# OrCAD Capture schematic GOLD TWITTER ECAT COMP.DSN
size A4; title: GTWIECAT
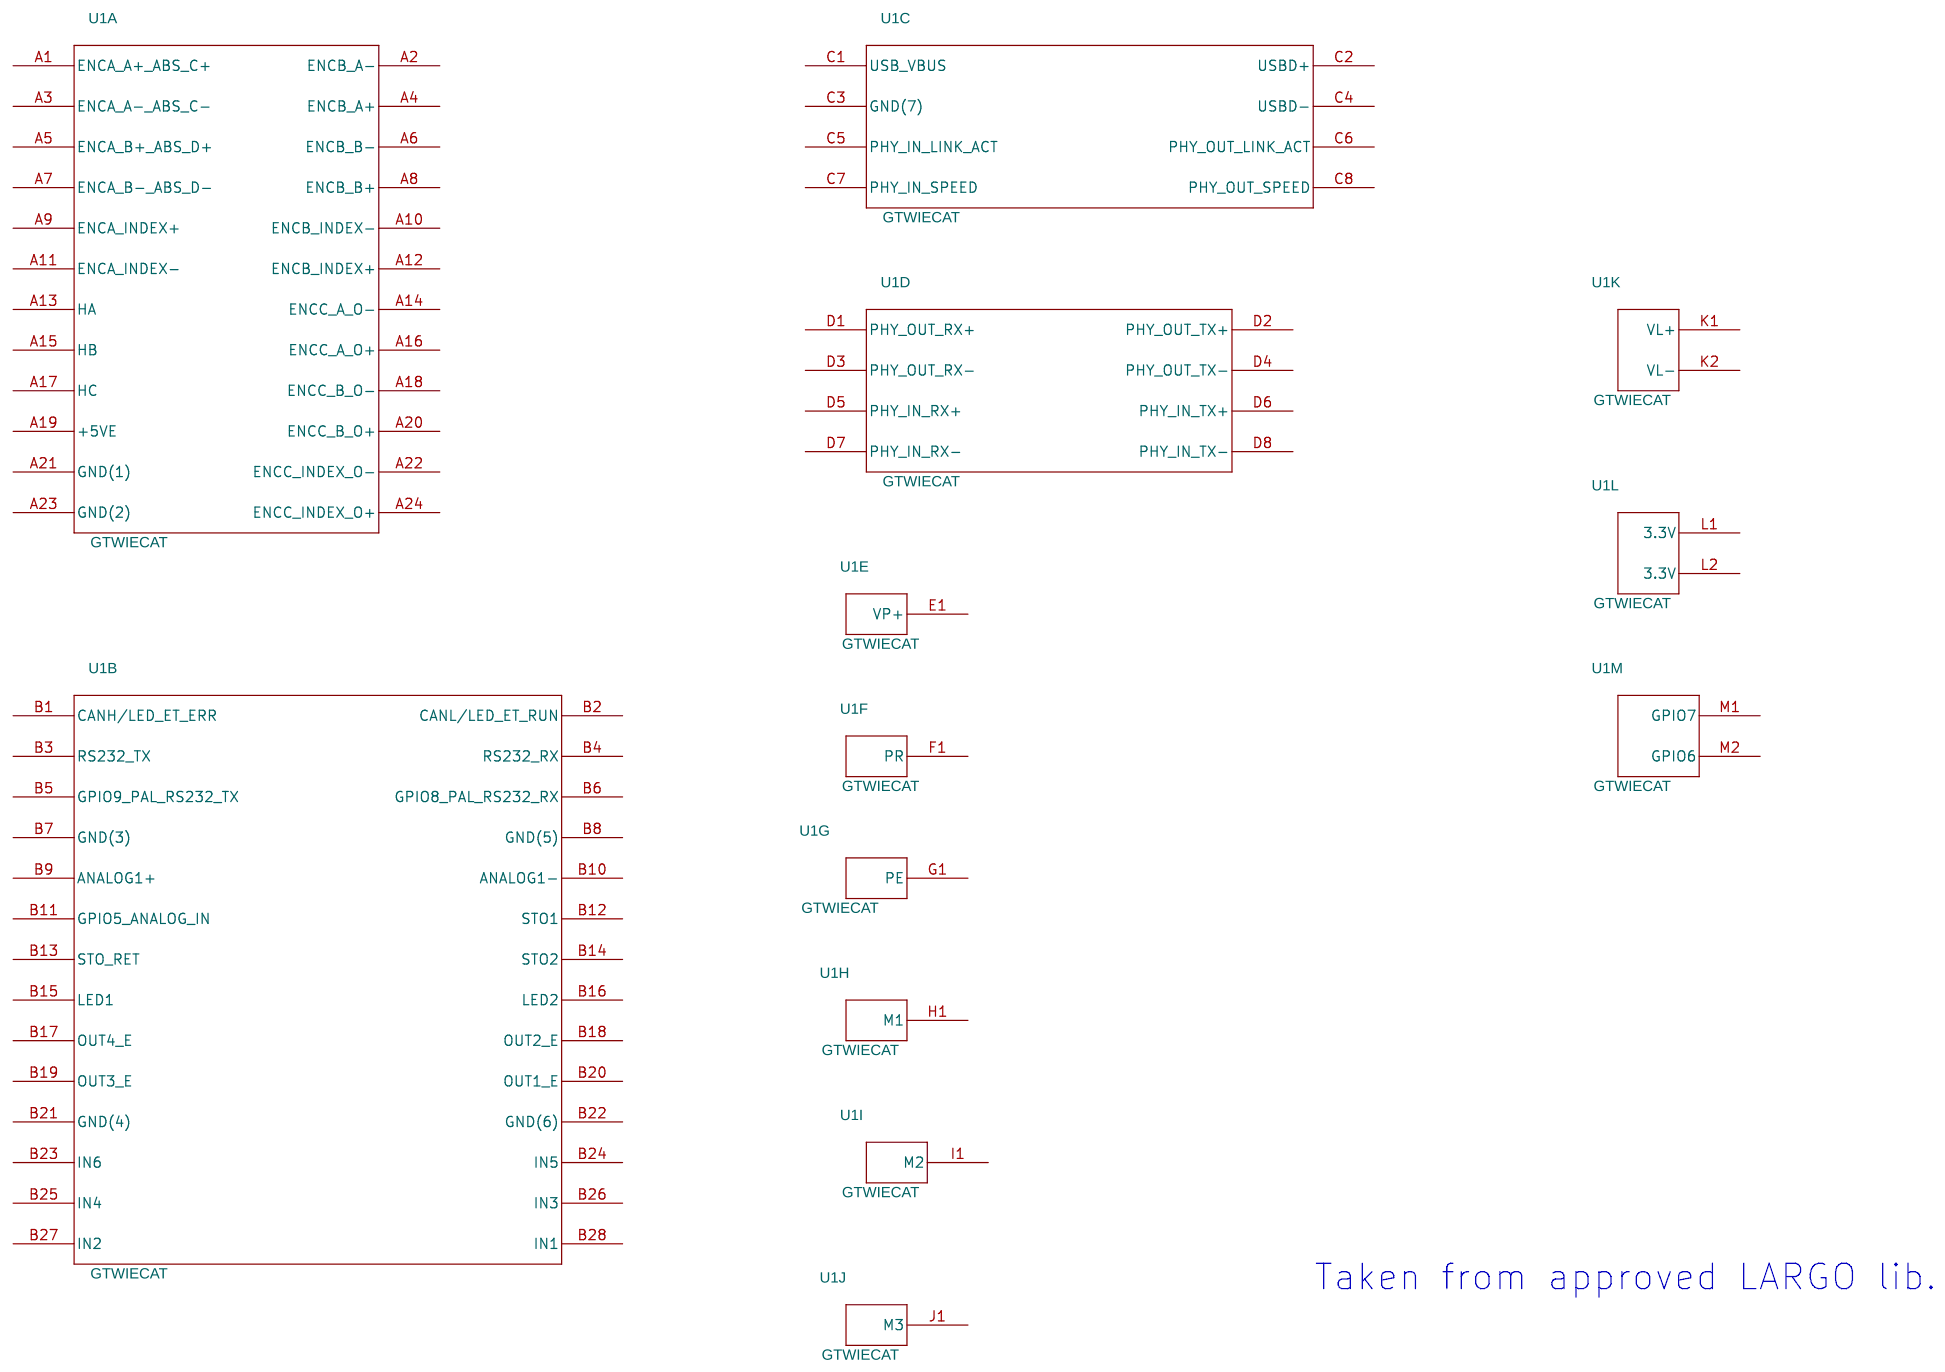
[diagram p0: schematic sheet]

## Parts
U1  GTWIECAT  [NANO_V1]  (sections A,B,C,D,E,F,G,H,I,J,K,L,M)

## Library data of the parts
U1 = GTWIECAT_GTWIECAT

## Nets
3.3V: U1.L1(3.3V) U1.L2(3.3V)
+5VE: U1.A19(+5VE)
GND(1): U1.A21(GND(1))
GND(2): U1.A23(GND(2))
GND(3): U1.B7(GND(3))
GND(4): U1.B21(GND(4))
GND(5): U1.B8(GND(5))
GND(6): U1.B22(GND(6))
GND(7): U1.C3(GND(7))
PE: U1.G1(PE)
PR: U1.F1(PR)
VL+: U1.K1(VL+)
VL-: U1.K2(VL-)
VP+: U1.E1(VP+)

Not connected (* = marked no-connect by the designer): U1 A1(ENCA_A+_ABS_C+) A2(ENCB_A-) A3(ENCA_A-_ABS_C-) A4(ENCB_A+) A5(ENCA_B+_ABS_D+) A6(ENCB_B-) A7(ENCA_B-_ABS_D-) A8(ENCB_B+) A9(ENCA_INDEX+) A10(ENCB_INDEX-) A11(ENCA_INDEX-) A12(ENCB_INDEX+) A13(HA) A14(ENCC_A_O-) A15(HB) A16(ENCC_A_O+) A17(HC) A18(ENCC_B_O-) A20(ENCC_B_O+) A22(ENCC_INDEX_O-) A24(ENCC_INDEX_O+) B1(CANH/LED_ET_ERR) B2(CANL/LED_ET_RUN) B3(RS232_TX) B4(RS232_RX) B5(GPIO9_PAL_RS232_TX) B6(GPIO8_PAL_RS232_RX) B9(ANALOG1+) B10(ANALOG1-) B11(GPIO5_ANALOG_IN) B12(STO1) B13(STO_RET) B14(STO2) B15(LED1) B16(LED2) B17(OUT4_E) B18(OUT2_E) B19(OUT3_E) B20(OUT1_E) B23(IN6) B24(IN5) B25(IN4) B26(IN3) B27(IN2) B28(IN1) C1(USB_VBUS) C2(USBD+) C4(USBD-) C5(PHY_IN_LINK_ACT) C6(PHY_OUT_LINK_ACT) C7(PHY_IN_SPEED) C8(PHY_OUT_SPEED) D1(PHY_OUT_RX+) D2(PHY_OUT_TX+) D3(PHY_OUT_RX-) D4(PHY_OUT_TX-) D5(PHY_IN_RX+) D6(PHY_IN_TX+) D7(PHY_IN_RX-) D8(PHY_IN_TX-) H1(M1) I1(M2) J1(M3) M1(GPIO7) M2(GPIO6)

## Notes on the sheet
- Taken from approved LARGO lib.
